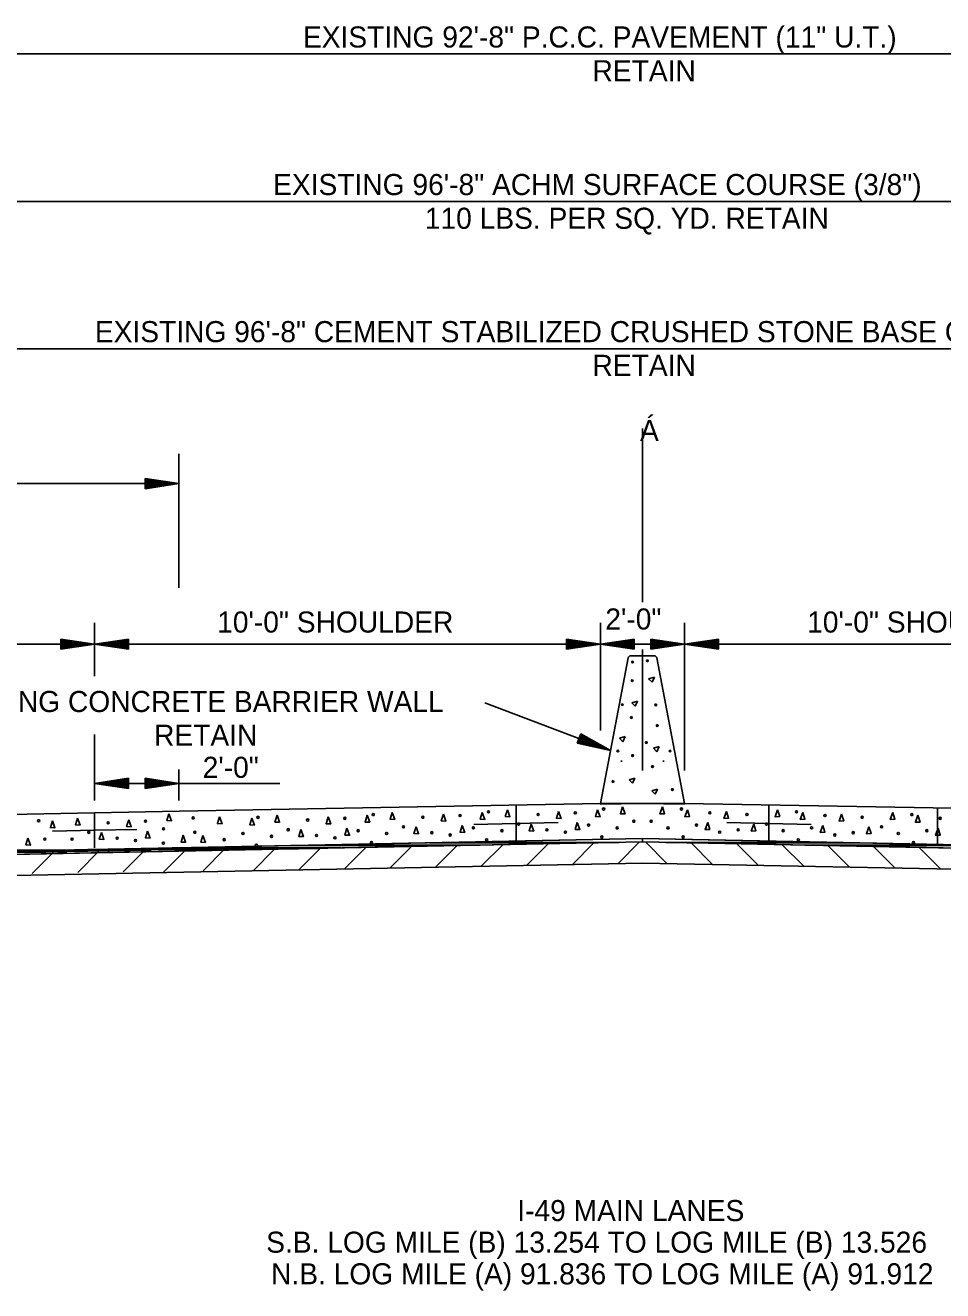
# Model space of a CAD drawing. Extents: x 60325 to 61047, y 53669 to 53767.
# Drawn here: x 60556.9 to 60578.67, y 53682.79 to 53712.8 of the extents above; entities that cross this region are included whole.
import ezdxf

# ---------------------------------------------------------------- set-up
doc = ezdxf.new("R2010")
doc.units = 0
doc.layers.add('R_Border', color=7, linetype='Continuous')
doc.layers.add('R_Border Prem', color=7, linetype='Continuous')

msp = doc.modelspace()

# ---------------------------------------------------------------- linework, layer by layer
at = {"layer": 'R_Border'}
for p, q in [((60571.545, 53699.117), (60571.545, 53703.239)), ((60560.545, 53699.462), (60560.545, 53702.635)), ((60559.745, 53702.049), (60560.545, 53701.929)), ((60559.745, 53701.809), (60559.745, 53702.049)), ((60559.745, 53702.029), (60560.412, 53701.929)), ((60559.745, 53702.009), (60560.274, 53701.929)), ((60559.745, 53701.989), (60560.141, 53701.929)), ((60532.545, 53701.929), (60560.545, 53701.929)), ((60559.745, 53701.969), (60560.005, 53701.929)), ((60559.745, 53701.948), (60559.872, 53701.929)), ((60559.745, 53701.809), (60560.545, 53701.929)), ((60559.745, 53701.891), (60560.005, 53701.929)), ((60559.745, 53701.85), (60560.274, 53701.929)), ((60559.745, 53701.829), (60560.412, 53701.929)), ((60559.745, 53701.87), (60560.141, 53701.929)), ((60559.745, 53701.911), (60559.872, 53701.929)), ((60558.545, 53697.359), (60558.545, 53698.624)), ((60570.545, 53696.073), (60570.545, 53698.624)), ((60572.545, 53695.124), (60572.545, 53698.624)), ((60546.545, 53698.124), (60558.545, 53698.124)), ((60557.745, 53698.244), (60558.545, 53698.124)), ((60557.745, 53698.004), (60557.745, 53698.244)), ((60557.745, 53698.224), (60558.412, 53698.124)), ((60557.745, 53698.204), (60558.274, 53698.124)), ((60557.745, 53698.184), (60558.141, 53698.124)), ((60557.745, 53698.164), (60558.005, 53698.124)), ((60557.745, 53698.143), (60557.872, 53698.124)), ((60557.745, 53698.004), (60558.545, 53698.124)), ((60557.745, 53698.086), (60558.005, 53698.124)), ((60557.745, 53698.045), (60558.274, 53698.124)), ((60557.745, 53698.024), (60558.412, 53698.124)), ((60557.745, 53698.065), (60558.141, 53698.124)), ((60557.745, 53698.106), (60557.872, 53698.124)), ((60559.345, 53698.244), (60558.545, 53698.124)), ((60570.545, 53698.124), (60558.545, 53698.124)), ((60559.345, 53698.004), (60558.545, 53698.124)), ((60559.345, 53698.224), (60558.679, 53698.124)), ((60559.345, 53698.024), (60558.679, 53698.124)), ((60559.345, 53698.204), (60558.816, 53698.124)), ((60559.345, 53698.045), (60558.816, 53698.124)), ((60559.345, 53698.184), (60558.95, 53698.124)), ((60559.345, 53698.065), (60558.95, 53698.124)), ((60559.345, 53698.163), (60559.085, 53698.124)), ((60559.345, 53698.085), (60559.085, 53698.124)), ((60559.345, 53698.143), (60559.219, 53698.124)), ((60559.345, 53698.106), (60559.219, 53698.124)), ((60559.345, 53698.244), (60559.345, 53698.004)), ((60569.745, 53698.244), (60570.545, 53698.124)), ((60569.745, 53698.244), (60569.745, 53698.004)), ((60569.745, 53698.224), (60570.412, 53698.124)), ((60569.745, 53698.204), (60570.274, 53698.124)), ((60569.745, 53698.184), (60570.141, 53698.124)), ((60569.745, 53698.163), (60570.005, 53698.124)), ((60569.745, 53698.143), (60569.872, 53698.124)), ((60569.745, 53698.004), (60570.545, 53698.124)), ((60569.745, 53698.085), (60570.005, 53698.124)), ((60569.745, 53698.045), (60570.274, 53698.124)), ((60569.745, 53698.024), (60570.412, 53698.124)), ((60569.745, 53698.065), (60570.141, 53698.124)), ((60569.745, 53698.106), (60569.872, 53698.124)), ((60573.345, 53698.244), (60572.545, 53698.124)), ((60572.545, 53698.124), (60584.545, 53698.124)), ((60573.345, 53698.004), (60572.545, 53698.124)), ((60573.345, 53698.224), (60572.679, 53698.124)), ((60573.345, 53698.024), (60572.679, 53698.124)), ((60573.345, 53698.204), (60572.816, 53698.124)), ((60573.345, 53698.045), (60572.816, 53698.124)), ((60573.345, 53698.184), (60572.95, 53698.124)), ((60573.345, 53698.065), (60572.95, 53698.124)), ((60573.345, 53698.163), (60573.085, 53698.124)), ((60573.345, 53698.085), (60573.085, 53698.124)), ((60573.345, 53698.143), (60573.219, 53698.124)), ((60573.345, 53698.106), (60573.219, 53698.124)), ((60573.345, 53698.244), (60573.345, 53698.004)), ((60571.545, 53695.124), (60571.545, 53697.993)), ((60558.545, 53694.411), (60558.545, 53695.979)), ((60560.545, 53694.411), (60560.545, 53695.146)), ((60559.345, 53694.94), (60558.545, 53694.82)), ((60560.545, 53694.82), (60558.545, 53694.82)), ((60559.345, 53694.7), (60558.545, 53694.82)), ((60559.345, 53694.92), (60558.679, 53694.82)), ((60559.345, 53694.72), (60558.679, 53694.82)), ((60559.345, 53694.899), (60558.816, 53694.82)), ((60559.345, 53694.74), (60558.816, 53694.82)), ((60559.345, 53694.879), (60558.95, 53694.82)), ((60559.345, 53694.76), (60558.95, 53694.82)), ((60559.345, 53694.858), (60559.085, 53694.82)), ((60559.345, 53694.78), (60559.085, 53694.82)), ((60559.345, 53694.838), (60559.219, 53694.82)), ((60559.345, 53694.801), (60559.219, 53694.82)), ((60559.345, 53694.94), (60559.345, 53694.7)), ((60559.745, 53694.94), (60560.545, 53694.82)), ((60559.745, 53694.94), (60559.745, 53694.7)), ((60559.745, 53694.92), (60560.412, 53694.82)), ((60559.745, 53694.899), (60560.274, 53694.82)), ((60559.745, 53694.879), (60560.141, 53694.82)), ((60559.745, 53694.858), (60560.005, 53694.82)), ((60559.745, 53694.838), (60559.872, 53694.82)), ((60559.745, 53694.7), (60560.545, 53694.82)), ((60559.745, 53694.78), (60560.005, 53694.82)), ((60559.745, 53694.74), (60560.274, 53694.82)), ((60559.745, 53694.72), (60560.412, 53694.82)), ((60559.745, 53694.76), (60560.141, 53694.82)), ((60559.745, 53694.801), (60559.872, 53694.82)), ((60562.939, 53694.82), (60560.545, 53694.82)), ((60558.545, 53694.124), (60558.545, 53693.291)), ((60558.545, 53693.708), (60557.545, 53693.688)), ((60559.545, 53693.728), (60558.545, 53693.708))]:
    msp.add_line(p, q, dxfattribs=at)
msp.add_lwpolyline([(60560.556, 53694.161), (60558.545, 53694.124), (60532.545, 53693.604)], dxfattribs=at)
at = {"layer": 'R_Border Prem'}
for p, q in [((60618.545, 53712.124), (60524.545, 53712.124)), ((60619.713, 53708.624), (60522.149, 53708.624)), ((60619.713, 53705.124), (60522.149, 53705.124)), ((60571.345, 53698.244), (60570.545, 53698.124)), ((60570.545, 53698.124), (60572.545, 53698.124)), ((60571.345, 53698.004), (60570.545, 53698.124)), ((60571.345, 53698.224), (60570.679, 53698.124)), ((60571.345, 53698.024), (60570.679, 53698.124)), ((60571.345, 53698.204), (60570.816, 53698.124)), ((60571.345, 53698.045), (60570.816, 53698.124)), ((60571.345, 53698.184), (60570.95, 53698.124)), ((60571.345, 53698.065), (60570.95, 53698.124)), ((60571.345, 53698.163), (60571.085, 53698.124)), ((60571.345, 53698.085), (60571.085, 53698.124)), ((60571.345, 53698.143), (60571.219, 53698.124)), ((60571.345, 53698.106), (60571.219, 53698.124)), ((60571.345, 53698.244), (60571.345, 53698.004)), ((60571.745, 53698.244), (60572.545, 53698.124)), ((60571.745, 53698.004), (60571.745, 53698.244)), ((60571.745, 53698.224), (60572.412, 53698.124)), ((60571.745, 53698.204), (60572.274, 53698.124)), ((60571.745, 53698.184), (60572.141, 53698.124)), ((60571.745, 53698.164), (60572.005, 53698.124)), ((60571.745, 53698.143), (60571.872, 53698.124)), ((60571.745, 53698.004), (60572.545, 53698.124)), ((60571.745, 53698.086), (60572.005, 53698.124)), ((60571.745, 53698.045), (60572.274, 53698.124)), ((60571.745, 53698.024), (60572.412, 53698.124)), ((60571.745, 53698.065), (60572.141, 53698.124)), ((60571.745, 53698.106), (60571.872, 53698.124)), ((60571.206, 53697.795), (60570.548, 53694.344)), ((60571.267, 53697.845), (60571.822, 53697.845)), ((60571.882, 53697.798), (60572.541, 53694.344)), ((60571.691, 53697.302), (60571.826, 53697.339)), ((60571.774, 53697.22), (60571.691, 53697.302)), ((60571.826, 53697.339), (60571.774, 53697.22)), ((60570.788, 53695.6), (60567.806, 53696.731)), ((60571.289, 53696.732), (60571.424, 53696.769)), ((60571.372, 53696.65), (60571.289, 53696.732)), ((60571.424, 53696.769), (60571.372, 53696.65)), ((60569.997, 53695.772), (60570.082, 53695.996)), ((60570.082, 53695.996), (60570.788, 53695.6)), ((60569.997, 53695.772), (60570.788, 53695.6)), ((60570.004, 53695.79), (60570.663, 53695.648)), ((60570.011, 53695.81), (60570.534, 53695.696)), ((60570.018, 53695.828), (60570.409, 53695.744)), ((60570.026, 53695.848), (60570.283, 53695.792)), ((60570.033, 53695.866), (60570.158, 53695.839)), ((60570.046, 53695.902), (60570.158, 53695.839)), ((60570.053, 53695.921), (60570.283, 53695.792)), ((60570.061, 53695.94), (60570.409, 53695.744)), ((60570.068, 53695.958), (60570.534, 53695.696)), ((60570.075, 53695.977), (60570.663, 53695.648)), ((60570.995, 53695.891), (60571.13, 53695.928)), ((60571.078, 53695.809), (60570.995, 53695.891)), ((60571.13, 53695.928), (60571.078, 53695.809)), ((60571.802, 53695.654), (60571.937, 53695.691)), ((60571.937, 53695.691), (60571.885, 53695.572)), ((60571.885, 53695.572), (60571.802, 53695.654)), ((60571.028, 53695.343), (60571.062, 53695.343)), ((60572.027, 53695.343), (60572.061, 53695.343)), ((60571.228, 53694.907), (60571.363, 53694.944)), ((60571.311, 53694.825), (60571.228, 53694.907)), ((60571.363, 53694.944), (60571.311, 53694.825)), ((60571.763, 53694.646), (60571.898, 53694.683)), ((60571.846, 53694.564), (60571.763, 53694.646)), ((60571.898, 53694.683), (60571.846, 53694.564)), ((60570.548, 53694.344), (60560.556, 53694.161)), ((60568.545, 53694.284), (60568.545, 53693.451)), ((60571.545, 53694.344), (60570.544, 53694.324)), ((60570.548, 53694.344), (60571.545, 53694.344)), ((60571.545, 53694.344), (60572.545, 53694.324)), ((60571.545, 53694.344), (60572.541, 53694.344)), ((60572.027, 53694.344), (60572.061, 53694.344)), ((60582.532, 53694.162), (60572.541, 53694.344)), ((60574.545, 53693.451), (60574.545, 53694.284)), ((60574.545, 53694.284), (60574.545, 53693.451)), ((60578.545, 53693.371), (60578.545, 53694.235)), ((60569.545, 53693.888), (60568.545, 53693.868)), ((60573.545, 53693.888), (60574.545, 53693.868)), ((60568.545, 53693.868), (60567.545, 53693.848)), ((60574.545, 53693.868), (60575.545, 53693.848)), ((60571.545, 53693.511), (60532.545, 53692.731)), ((60571.545, 53693.431), (60532.545, 53692.651)), ((60564.386, 53693.288), (60560.385, 53693.288)), ((60567.19, 53693.344), (60563.189, 53693.344)), ((60567.69, 53693.354), (60563.689, 53693.354)), ((60564.981, 53693.3), (60564.471, 53692.789)), ((60566.063, 53693.321), (60565.553, 53692.811)), ((60570.494, 53693.41), (60566.493, 53693.41)), ((60567.146, 53693.343), (60566.635, 53692.833)), ((60570.994, 53693.42), (60566.993, 53693.42)), ((60568.228, 53693.365), (60567.718, 53692.854)), ((60569.31, 53693.386), (60568.8, 53692.876)), ((60570.393, 53693.408), (60569.882, 53692.898)), ((60571.475, 53693.43), (60570.965, 53692.919)), ((60571.545, 53693.511), (60610.545, 53692.731)), ((60571.545, 53693.431), (60610.545, 53692.651)), ((60571.615, 53693.43), (60572.126, 53692.919)), ((60572.096, 53693.42), (60576.097, 53693.42)), ((60572.596, 53693.41), (60576.597, 53693.41)), ((60572.698, 53693.408), (60573.208, 53692.898)), ((60573.78, 53693.386), (60574.29, 53692.876)), ((60574.862, 53693.365), (60575.373, 53692.854)), ((60575.4, 53693.354), (60579.401, 53693.354)), ((60575.9, 53693.344), (60579.901, 53693.344)), ((60575.945, 53693.343), (60576.455, 53692.833)), ((60577.027, 53693.321), (60577.537, 53692.811)), ((60578.109, 53693.3), (60578.619, 53692.789)), ((60557.386, 53693.188), (60553.385, 53693.188)), ((60557.886, 53693.198), (60553.885, 53693.198)), ((60558.386, 53693.208), (60554.385, 53693.208)), ((60558.886, 53693.218), (60554.885, 53693.218)), ((60559.386, 53693.228), (60555.385, 53693.228)), ((60559.886, 53693.238), (60555.885, 53693.238)), ((60557.57, 53693.191), (60557.059, 53692.681)), ((60558.648, 53693.209), (60558.142, 53692.703)), ((60562.386, 53693.248), (60558.385, 53693.248)), ((60562.886, 53693.258), (60558.885, 53693.258)), ((60559.734, 53693.235), (60559.224, 53692.724)), ((60563.386, 53693.268), (60559.385, 53693.268)), ((60563.886, 53693.278), (60559.885, 53693.278)), ((60560.688, 53693.221), (60560.177, 53692.711)), ((60561.626, 53693.256), (60561.116, 53692.746)), ((60562.816, 53693.256), (60562.306, 53692.746)), ((60563.899, 53693.278), (60563.388, 53692.768)), ((60571.545, 53692.931), (60532.542, 53692.151)), ((60571.545, 53692.931), (60610.502, 53692.152))]:
    msp.add_line(p, q, dxfattribs=at)
for points in [[(60568.338, 53694.196), (60568.398, 53694.03), (60568.288, 53694.035), (60568.338, 53694.196)], [(60570.476, 53694.196), (60570.537, 53694.03), (60570.427, 53694.035), (60570.476, 53694.196)], [(60571.071, 53694.262), (60571.132, 53694.096), (60571.022, 53694.101), (60571.071, 53694.262)], [(60572.019, 53694.262), (60571.959, 53694.096), (60572.069, 53694.101), (60572.019, 53694.262)], [(60572.614, 53694.196), (60572.553, 53694.03), (60572.663, 53694.035), (60572.614, 53694.196)], [(60574.752, 53694.196), (60574.692, 53694.03), (60574.802, 53694.035), (60574.752, 53694.196)], [(60557.544, 53693.932), (60557.604, 53693.766), (60557.494, 53693.771), (60557.544, 53693.932)], [(60558.138, 53693.998), (60558.199, 53693.832), (60558.089, 53693.837), (60558.138, 53693.998)], [(60559.353, 53693.958), (60559.414, 53693.792), (60559.304, 53693.796), (60559.353, 53693.958)], [(60560.308, 53694.1), (60560.369, 53693.934), (60560.259, 53693.938), (60560.308, 53694.1)], [(60561.508, 53694.027), (60561.569, 53693.861), (60561.459, 53693.865), (60561.508, 53694.027)], [(60562.277, 53693.998), (60562.337, 53693.832), (60562.227, 53693.837), (60562.277, 53693.998)], [(60562.872, 53694.064), (60562.932, 53693.898), (60562.822, 53693.903), (60562.872, 53694.064)], [(60564.087, 53694.024), (60564.147, 53693.858), (60564.037, 53693.862), (60564.087, 53694.024)], [(60565.01, 53694.064), (60565.071, 53693.898), (60564.961, 53693.903), (60565.01, 53694.064)], [(60565.605, 53694.13), (60565.665, 53693.964), (60565.555, 53693.969), (60565.605, 53694.13)], [(60566.82, 53694.09), (60566.88, 53693.924), (60566.77, 53693.928), (60566.82, 53694.09)], [(60567.743, 53694.13), (60567.804, 53693.964), (60567.694, 53693.969), (60567.743, 53694.13)], [(60569.553, 53694.156), (60569.613, 53693.99), (60569.503, 53693.994), (60569.553, 53694.156)], [(60569.998, 53693.889), (60570.059, 53693.723), (60569.949, 53693.727), (60569.998, 53693.889)], [(60573.092, 53693.889), (60573.031, 53693.723), (60573.141, 53693.727), (60573.092, 53693.889)], [(60573.537, 53694.156), (60573.477, 53693.99), (60573.587, 53693.994), (60573.537, 53694.156)], [(60575.347, 53694.13), (60575.287, 53693.964), (60575.397, 53693.969), (60575.347, 53694.13)], [(60576.27, 53694.09), (60576.21, 53693.924), (60576.32, 53693.928), (60576.27, 53694.09)], [(60577.485, 53694.13), (60577.425, 53693.964), (60577.535, 53693.969), (60577.485, 53694.13)], [(60578.08, 53694.064), (60578.02, 53693.898), (60578.13, 53693.903), (60578.08, 53694.064)], [(60558.705, 53693.658), (60558.766, 53693.492), (60558.656, 53693.496), (60558.705, 53693.658)], [(60559.799, 53693.69), (60559.859, 53693.524), (60559.749, 53693.529), (60559.799, 53693.69)], [(60560.644, 53693.589), (60560.704, 53693.423), (60560.594, 53693.428), (60560.644, 53693.589)], [(60561.115, 53693.584), (60561.175, 53693.418), (60561.065, 53693.423), (60561.115, 53693.584)], [(60563.439, 53693.724), (60563.499, 53693.558), (60563.389, 53693.563), (60563.439, 53693.724)], [(60564.532, 53693.756), (60564.593, 53693.59), (60564.483, 53693.595), (60564.532, 53693.756)], [(60566.172, 53693.79), (60566.232, 53693.624), (60566.122, 53693.629), (60566.172, 53693.79)], [(60567.265, 53693.822), (60567.326, 53693.656), (60567.216, 53693.661), (60567.265, 53693.822)], [(60568.905, 53693.856), (60568.965, 53693.69), (60568.855, 53693.695), (60568.905, 53693.856)], [(60574.185, 53693.856), (60574.125, 53693.69), (60574.235, 53693.695), (60574.185, 53693.856)], [(60575.825, 53693.822), (60575.764, 53693.656), (60575.874, 53693.661), (60575.825, 53693.822)], [(60576.918, 53693.79), (60576.858, 53693.624), (60576.968, 53693.629), (60576.918, 53693.79)], [(60578.558, 53693.756), (60578.498, 53693.59), (60578.608, 53693.595), (60578.558, 53693.756)], [(60556.962, 53693.522), (60557.023, 53693.356), (60556.913, 53693.361), (60556.962, 53693.522)]]:
    msp.add_lwpolyline(points, dxfattribs=at)
for points in [[(60571.545, 53693.511), (60548.545, 53693.051), (60548.545, 53692.971), (60571.545, 53693.431)], [(60571.545, 53693.511), (60594.545, 53693.051), (60594.545, 53692.971), (60571.545, 53693.431)]]:
    msp.add_lwpolyline(points, close=True, dxfattribs=at)
for centre in [(60570.622, 53694.212), (60572.468, 53694.212), (60557.216, 53693.934), (60558.867, 53693.884), (60559.75, 53693.924), (60560.884, 53694), (60562.422, 53694.013), (60563.6, 53693.95), (60564.483, 53693.99), (60565.156, 53694.079), (60566.334, 53694.016), (60567.216, 53694.056), (60567.889, 53694.146), (60569.067, 53694.082), (60569.95, 53694.123), (60571.338, 53693.921), (60571.752, 53693.921), (60573.141, 53694.123), (60574.024, 53694.082), (60575.201, 53694.146), (60575.874, 53694.056), (60576.757, 53694.016), (60577.935, 53694.079), (60578.607, 53693.99), (60558.405, 53693.657), (60560.18, 53693.742), (60560.923, 53693.66), (60562.066, 53693.633), (60562.742, 53693.564), (60563.139, 53693.723), (60563.811, 53693.585), (60564.799, 53693.699), (60565.475, 53693.631), (60565.872, 53693.789), (60566.544, 53693.651), (60566.982, 53693.595), (60567.532, 53693.765), (60568.209, 53693.697), (60568.605, 53693.855), (60569.277, 53693.717), (60569.715, 53693.661), (60570.266, 53693.831), (60570.942, 53693.763), (60572.149, 53693.763), (60572.825, 53693.831), (60573.376, 53693.661), (60573.813, 53693.717), (60574.485, 53693.855), (60574.882, 53693.697), (60575.558, 53693.765), (60576.109, 53693.595), (60576.546, 53693.651), (60577.218, 53693.789), (60577.615, 53693.631), (60578.291, 53693.699), (60557.361, 53693.498), (60558.009, 53693.498), (60559.078, 53693.519), (60559.515, 53693.463), (60560.175, 53693.402), (60561.618, 53693.485), (60562.382, 53693.349), (60564.248, 53693.529), (60565.115, 53693.415), (60567.848, 53693.481), (60570.581, 53693.547), (60572.509, 53693.547), (60575.242, 53693.481), (60577.975, 53693.415)]:
    msp.add_circle(centre, 0.025, dxfattribs=at)
for centre, start_param, end_param in [((60571.267, 53697.784), 0, 1.382575), ((60571.822, 53697.784), 4.902487, 6.283185)]:
    msp.add_ellipse(centre, major_axis=(0, 0.0619), ratio=0.9997, start_param=start_param, end_param=end_param, dxfattribs=at)
for centre in [(60571.309, 53697.699), (60571.659, 53697.729), (60571.301, 53697.255), (60571.065, 53696.688), (60571.859, 53696.682), (60571.279, 53696.382), (60571.894, 53696.191), (60571.635, 53695.787), (60570.959, 53695.589), (60571.309, 53695.479), (60572.197, 53695.589), (60571.782, 53695.218), (60570.846, 53694.864), (60572.254, 53694.672)]:
    msp.add_ellipse(centre, major_axis=(0, 0.0205), ratio=0.9997, dxfattribs=at)

# ---------------------------------------------------------------- texts
at = {"layer": 'R_Border'}
for s, p in [('Á', (60571.486, 53702.94)), ('10\'-0" SHOULDER', (60561.452, 53698.397)), ('10\'-0" SHOULDER', (60575.452, 53698.397)), ('2\'-0"', (60561.108, 53694.951)), ('I-49 MAIN LANES', (60568.573, 53684.437)), ('S.B. LOG MILE (B) 13.254 TO LOG MILE (B) 13.526', (60562.615, 53683.687)), ('N.B. LOG MILE (A) 91.836 TO LOG MILE (A) 91.912', (60562.731, 53682.937))]:
    msp.add_text(s, height=0.5, dxfattribs=at).set_placement(p)
at = {"layer": 'R_Border Prem'}
for s, p in [('EXISTING 92\'-8" P.C.C. PAVEMENT (11" U.T.)', (60563.487, 53712.274)), ('RETAIN', (60570.358, 53711.474)), ('EXISTING 96\'-8" ACHM SURFACE COURSE (3/8")', (60562.779, 53708.774)), ('110 LBS. PER SQ. YD. RETAIN', (60566.379, 53707.974)), ('EXISTING 96\'-8" CEMENT STABILIZED CRUSHED STONE BASE COURSE', (60558.55, 53705.285)), ('RETAIN', (60570.358, 53704.485)), ('2\'-0"', (60570.662, 53698.469)), ('EXISTING CONCRETE BARRIER WALL', (60554.605, 53696.512)), ('RETAIN', (60559.955, 53695.712))]:
    msp.add_text(s, height=0.5, dxfattribs=at).set_placement(p)

doc.saveas('drawing.dxf')
